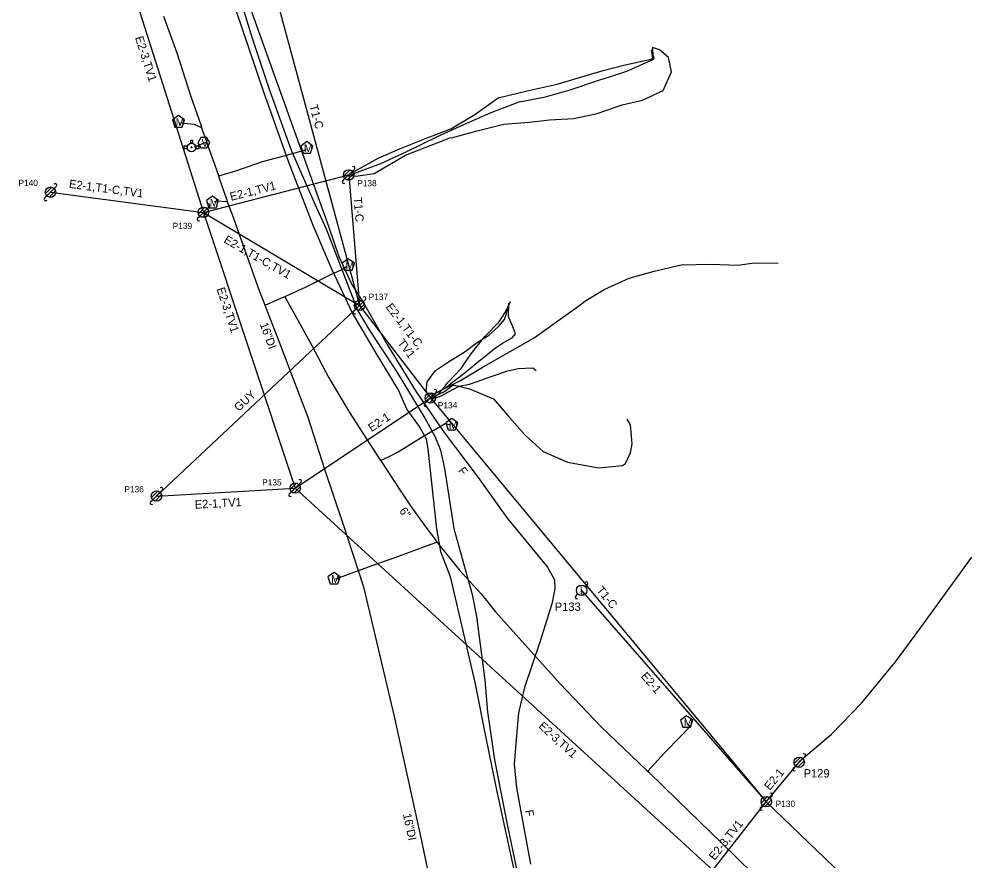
# Model space of a CAD drawing. Extents: x 1741604 to 1825760, y 1164229 to 1194908.
# Drawn here: x 1754886.6 to 1755346.9, y 1170509.7 to 1170914.1 of the extents above; entities that cross this region are included whole.
import ezdxf

# ---------------------------------------------------------------- set-up
doc = ezdxf.new("R2010")
doc.units = 0
for name, color, linetype in [('RD_EX_SU_Elec', 7, 'Continuous'), ('RD_EX_SU_H2O', 7, 'Continuous'), ('RD_EX_SU_Ovhd', 7, 'Continuous'), ('RD_EX_SU_Pole', 7, 'Continuous'), ('RD_EX_SU_Telecom', 7, 'Continuous'), ('RD_EX_SU_TX_H2O', 7, 'Continuous'), ('RD_EX_SU_TX_Pole', 7, 'Continuous'), ('RD_EX_SU_TX_Telecom', 7, 'Continuous')]:
    doc.layers.add(name, color=color, linetype=linetype)

# ---------------------------------------------------------------- blocks, each defined once
blk = doc.blocks.new('SUE_PP')
at = {"layer": 'RD_EX_SU_Pole'}
for p, q in [((-2.41, -0.65), (0.65, 2.41)), ((-1.77, -1.77), (1.77, 1.77)), ((-0.65, -2.41), (2.41, 0.65)), ((1.77, 1.77), (2.83, 2.83)), ((-2.83, -2.83), (-1.77, -1.77))]:
    blk.add_line(p, q, dxfattribs=at)
blk.add_circle((0, 0), 2.5, dxfattribs=at)
for centre, start, end in [((2.3, 3.36), 315, 135), ((-2.3, -3.36), 135, 315)]:
    blk.add_arc(centre, 0.75, start, end, dxfattribs=at)

msp = doc.modelspace()

# ---------------------------------------------------------------- linework, layer by layer
at = {"layer": 'RD_EX_SU_Elec'}
for points in [[(1755044.7, 1170839.23), (1755059.42, 1170847.52), (1755069.97, 1170851.99), (1755081.97, 1170856.73), (1755094.15, 1170861.35), (1755105.68, 1170868.24), (1755116.83, 1170876.23), (1755130.76, 1170879.59), (1755145.27, 1170882.79), (1755157.04, 1170886.35), (1755167.37, 1170889.4), (1755177.92, 1170892.19), (1755190.42, 1170894.89), (1755191.27, 1170895.37), (1755190.53, 1170899.32)], [(1755084.76, 1170733.42), (1755089.15, 1170735.61), (1755098.48, 1170740.34), (1755109.16, 1170746.7), (1755118.99, 1170752.35), (1755127.51, 1170757.14), (1755134.1, 1170760.96), (1755146.67, 1170769.95), (1755155.55, 1170776.25), (1755158.59, 1170778.65), (1755167.83, 1170784.2), (1755179.88, 1170789.61), (1755191.9, 1170793.03), (1755204.81, 1170796.12), (1755219.13, 1170796.38), (1755232.05, 1170795.84), (1755239.93, 1170796.97), (1755251.49, 1170796.86)], [(1755084.91, 1170731.92), (1755087.35, 1170733.19), (1755090.32, 1170736.35), (1755092.73, 1170739.5), (1755099.15, 1170746.28), (1755103.76, 1170753.16), (1755110.39, 1170761.57), (1755117.38, 1170768.69), (1755120.2, 1170773.08), (1755122.8, 1170778.49)], [(1755084.11, 1170731.83), (1755085.97, 1170731.91), (1755088.75, 1170732.77), (1755092.98, 1170735.1), (1755098.13, 1170737.74), (1755103.12, 1170738.67), (1755106.73, 1170740), (1755113.51, 1170742.36), (1755121.53, 1170745.15), (1755126.71, 1170746.19), (1755133.52, 1170746.54), (1755135.08, 1170745.23)], [(1755261.47, 1170557.34), (1755277.07, 1170570.46), (1755291.51, 1170585.36), (1755307.86, 1170605.28), (1755320.07, 1170621.78), (1755344.55, 1170655.55)]]:
    msp.add_lwpolyline(points, dxfattribs=at)
at = {"layer": 'RD_EX_SU_H2O'}
for p, q in [((1754967.44, 1170853.08), (1754965.8, 1170853.08)), ((1754965.8, 1170853.08), (1754965.8, 1170852.03)), ((1754968.97, 1170855.86), (1754968.97, 1170854.52)), ((1754970.02, 1170855.86), (1754968.97, 1170855.86)), ((1754970.02, 1170854.49), (1754970.02, 1170855.86)), ((1754970.88, 1170852.82), (1754976.78, 1170855.16)), ((1754973.15, 1170853.08), (1754971.46, 1170853.08)), ((1754973.15, 1170852.03), (1754973.15, 1170853.08)), ((1754965.8, 1170852.03), (1754967.4, 1170852.03)), ((1754971.5, 1170852.03), (1754973.15, 1170852.03))]:
    msp.add_line(p, q, dxfattribs=at)
for points in [[(1754956.06, 1170915.61), (1754962.38, 1170897.97), (1754969.17, 1170876.92), (1754973.9, 1170863.31), (1754974.6, 1170860.97), (1754976.54, 1170856.02), (1754977.05, 1170854.22), (1754979.81, 1170846.24), (1754982.34, 1170839.52), (1754982.8, 1170837.72), (1754986.07, 1170828.02), (1754986.99, 1170825.47), (1754988.93, 1170820.19), (1755002.08, 1170783.29), (1755004.4, 1170777.61), (1755005.1, 1170775.84), (1755011.46, 1170759.4), (1755019.59, 1170737.92), (1755025.36, 1170722.87), (1755033.31, 1170697.84), (1755042.14, 1170671.77)], [(1754963.77, 1170864.49), (1754965.97, 1170864.08), (1754970.66, 1170863.71), (1754974.26, 1170862.11)], [(1754982.53, 1170838.76), (1754990.75, 1170841.23), (1755003.57, 1170845.66), (1755016.43, 1170849.11), (1755024.71, 1170851.52)], [(1754986.66, 1170826.38), (1754981.58, 1170826.63), (1754980.39, 1170826.13)], [(1755004.79, 1170776.74), (1755012.45, 1170780.01), (1755015.18, 1170781.14), (1755024.31, 1170785.39), (1755037.39, 1170791.92), (1755041.3, 1170793.55), (1755044.15, 1170795.36)], [(1755014.24, 1170780.75), (1755019.67, 1170771.18), (1755027.37, 1170757.25), (1755035.4, 1170741.69), (1755045.44, 1170725.1), (1755059.91, 1170702.52), (1755060.75, 1170701.38), (1755069.67, 1170687.97), (1755075.12, 1170679.72), (1755082.62, 1170669.44), (1755086.66, 1170663.95), (1755087.69, 1170662.44), (1755098.04, 1170649.52), (1755108.67, 1170637.95), (1755115.51, 1170629.29), (1755146.69, 1170594.66), (1755166.41, 1170574.06), (1755188.2, 1170553.24), (1755189.2, 1170552.26), (1755202.99, 1170538.84), (1755224.11, 1170518.52), (1755246.97, 1170496)], [(1755060.31, 1170701.97), (1755064.52, 1170704.03), (1755068.81, 1170706.14), (1755080.57, 1170713.54), (1755091.39, 1170719.75), (1755093.83, 1170719.16)], [(1755042.14, 1170671.77), (1755052.06, 1170641.32), (1755066.9, 1170578.97), (1755079.96, 1170519.29), (1755092.63, 1170458.3), (1755105.45, 1170397.86), (1755116.43, 1170325.12), (1755123.37, 1170260.52), (1755129.9, 1170197.98), (1755130.76, 1170187.84), (1755130.94, 1170186.34), (1755135.98, 1170128.29), (1755137.6, 1170105.08), (1755122.59, 1170093.04)], [(1755038.81, 1170645.21), (1755056.35, 1170651.65), (1755068.64, 1170655.9), (1755082.42, 1170661), (1755087.41, 1170662.85)], [(1755188.74, 1170552.71), (1755196.87, 1170561.52), (1755204.69, 1170569.58), (1755209.12, 1170574.23), (1755207.59, 1170575.88)]]:
    msp.add_lwpolyline(points, dxfattribs=at)
for points in [[(1754963.21, 1170867.78), (1754960.3, 1170865.67), (1754961.41, 1170862.26), (1754965, 1170862.26), (1754966.11, 1170865.67)], [(1754978.33, 1170854.71), (1754976.89, 1170857.21), (1754974, 1170857.21), (1754972.56, 1170854.71), (1754974, 1170852.21), (1754976.89, 1170852.21)], [(1755024.87, 1170855.24), (1755021.97, 1170853.13), (1755023.08, 1170849.72), (1755026.66, 1170849.72), (1755027.77, 1170853.13)], [(1754979.59, 1170829.03), (1754976.69, 1170826.92), (1754977.8, 1170823.51), (1754981.38, 1170823.51), (1754982.49, 1170826.92)], [(1755044.83, 1170798.96), (1755041.93, 1170796.85), (1755043.04, 1170793.44), (1755046.62, 1170793.44), (1755047.73, 1170796.85)], [(1755094.56, 1170722.28), (1755091.66, 1170720.17), (1755092.76, 1170716.76), (1755096.35, 1170716.76), (1755097.46, 1170720.17)], [(1755037.96, 1170648.25), (1755035.06, 1170646.14), (1755036.17, 1170642.73), (1755039.75, 1170642.73), (1755040.86, 1170646.14)], [(1755207.46, 1170579.4), (1755204.56, 1170577.29), (1755205.67, 1170573.88), (1755209.26, 1170573.88), (1755210.36, 1170577.29)]]:
    msp.add_lwpolyline(points, close=True, dxfattribs=at)
for radius in [2.1, 0.263]:
    msp.add_circle((1754969.45, 1170852.47), radius, dxfattribs=at)
for start, end in [(163.3387, 192.315), (74.2455, 103.2128), (347.685, 16.6613)]:
    msp.add_arc((1754969.45, 1170852.47), 2.1, start, end, dxfattribs=at)
at = {"layer": 'RD_EX_SU_Ovhd'}
for p, q in [((1754936.53, 1170943.16), (1754975.2, 1170821.28)), ((1755009.84, 1170925.6), (1755050.22, 1170776.56)), ((1754975.2, 1170821.28), (1755045, 1170839.26)), ((1755045, 1170839.26), (1755050.22, 1170776.56)), ((1754901.67, 1170830.96), (1754975.2, 1170821.28)), ((1754975.2, 1170821.28), (1755050.22, 1170776.56)), ((1754975.2, 1170821.28), (1755019.3, 1170688.81)), ((1754952.64, 1170684.97), (1755050.22, 1170776.56)), ((1755050.22, 1170776.56), (1755084.28, 1170732.08)), ((1755019.3, 1170688.81), (1755084.28, 1170732.08)), ((1755084.28, 1170732.08), (1755245.71, 1170538.1)), ((1754952.64, 1170684.97), (1755019.3, 1170688.81)), ((1755019.3, 1170688.81), (1755220.03, 1170505.23)), ((1755156.98, 1170639.65), (1755245.71, 1170538.1)), ((1755245.71, 1170538.1), (1755261.53, 1170557.04)), ((1755220.03, 1170505.23), (1755245.71, 1170538.1)), ((1755245.71, 1170538.1), (1755346.94, 1170440.97))]:
    msp.add_line(p, q, dxfattribs=at)
at = {"layer": 'RD_EX_SU_Pole'}
for p, q in [((1755042.58, 1170838.61), (1755045.65, 1170841.68)), ((1755043.23, 1170837.49), (1755046.77, 1170841.03)), ((1755044.35, 1170836.85), (1755047.41, 1170839.91)), ((1755046.77, 1170841.03), (1755047.83, 1170842.09)), ((1755042.17, 1170836.43), (1755043.23, 1170837.49)), ((1755081.87, 1170731.43), (1755084.93, 1170734.49)), ((1755082.51, 1170730.31), (1755086.05, 1170733.84)), ((1755086.05, 1170733.84), (1755087.11, 1170734.9)), ((1755081.45, 1170729.25), (1755082.51, 1170730.31)), ((1755083.63, 1170729.66), (1755086.7, 1170732.72)), ((1755158.75, 1170641.42), (1755159.81, 1170642.48)), ((1755154.15, 1170636.83), (1755155.21, 1170637.89))]:
    msp.add_line(p, q, dxfattribs=at)
for centre in [(1755045, 1170839.26), (1755084.28, 1170732.08), (1755156.98, 1170639.65)]:
    msp.add_circle(centre, 2.5, dxfattribs=at)
for centre, start, end in [((1755047.3, 1170842.62), 315, 135), ((1755042.7, 1170835.9), 135, 315), ((1755086.58, 1170735.43), 315, 135), ((1755081.98, 1170728.72), 135, 315), ((1755159.28, 1170643.01), 315, 135), ((1755154.68, 1170636.3), 135, 315)]:
    msp.add_arc(centre, 0.75, start, end, dxfattribs=at)
at = {"layer": 'RD_EX_SU_Telecom'}
for points in [[(1754967.13, 1170994.05), (1754974.43, 1170968.95), (1754987.04, 1170929.46), (1755004.13, 1170879.16), (1755015.94, 1170845.8), (1755027.84, 1170815.17), (1755036.74, 1170794.1), (1755046.9, 1170772.73), (1755058.13, 1170753.54), (1755068.96, 1170735.75), (1755072.88, 1170726.57), (1755079.23, 1170717.91), (1755082.2, 1170712.4), (1755082.99, 1170707.43), (1755087.24, 1170669.18), (1755089.17, 1170658.27), (1755093.84, 1170646.29), (1755105.7, 1170595.36), (1755111, 1170568.73), (1755116.38, 1170542.14), (1755124.51, 1170504.65), (1755130.68, 1170470.03), (1755139.68, 1170422.81)], [(1754989.66, 1170942.34), (1755001.61, 1170908.39), (1755035.52, 1170814.23), (1755040.32, 1170800.04), (1755046.58, 1170786.61), (1755052.71, 1170776.7), (1755063.97, 1170756.98), (1755077.38, 1170735), (1755090.96, 1170715.53), (1755107.27, 1170693.89), (1755121.25, 1170674.35), (1755140.61, 1170650.74), (1755144.01, 1170644.65), (1755144.02, 1170640.39), (1755142.64, 1170633.11), (1755137.09, 1170615.19), (1755129.59, 1170592.91), (1755126.56, 1170580.85), (1755125.53, 1170568), (1755124.55, 1170556.1), (1755125.66, 1170544.73), (1755132.36, 1170508.03)], [(1754990.73, 1170930.67), (1754998.66, 1170905.01), (1755006.82, 1170880.46), (1755017.33, 1170851.11), (1755028.92, 1170824.86), (1755034.21, 1170813.32), (1755042.89, 1170790.87), (1755049.31, 1170774.25), (1755054.9, 1170764.86), (1755068.27, 1170744.38), (1755081.53, 1170722.42), (1755086.38, 1170713.73), (1755089.14, 1170706.97), (1755091.1, 1170698.27), (1755095.61, 1170669.4), (1755104.32, 1170637.7), (1755106.48, 1170627.02), (1755110.45, 1170596.46), (1755111.79, 1170581.3), (1755115.03, 1170558.13), (1755121.12, 1170527.09), (1755125.84, 1170504.97)], [(1755044.96, 1170839.04), (1755060.53, 1170844.8), (1755072.63, 1170850.4), (1755087.77, 1170857.76), (1755100.36, 1170863.53), (1755113.43, 1170869.18), (1755127.03, 1170874.33), (1755139.59, 1170876.74), (1755151.97, 1170880.24), (1755165.7, 1170884.94), (1755169.93, 1170886.23), (1755178.63, 1170889.07), (1755190.93, 1170894.56), (1755191.88, 1170895.42), (1755191.31, 1170896.87), (1755191.14, 1170900.26)], [(1755045.16, 1170839.16), (1755048.5, 1170838.63), (1755057.3, 1170839.89), (1755072.32, 1170848.71), (1755094.13, 1170857.27), (1755094.38, 1170857.14), (1755106.77, 1170860.49), (1755119.62, 1170863.63), (1755131.82, 1170864.59), (1755141.51, 1170865.71), (1755153.27, 1170866.37), (1755164.52, 1170868.73), (1755176.53, 1170872.91), (1755186.28, 1170875.11), (1755196.1, 1170879.88), (1755200.25, 1170888.75), (1755198.69, 1170895.74), (1755194.47, 1170899.35), (1755190.97, 1170900.47)], [(1755083.67, 1170732.7), (1755082.24, 1170735.28), (1755082.78, 1170739.91), (1755086.8, 1170745.28), (1755093.03, 1170749.4), (1755101, 1170754.35), (1755106.35, 1170758.4), (1755112.23, 1170762.1), (1755116.99, 1170766.45), (1755119.87, 1170769.79), (1755120.86, 1170772.65), (1755121.48, 1170775.76)], [(1755085.29, 1170733.01), (1755087.12, 1170734.51), (1755089.36, 1170735.75), (1755091.98, 1170737.24), (1755094.99, 1170739.85), (1755098.08, 1170742.02), (1755103.7, 1170746.53), (1755106.76, 1170749.14), (1755109.65, 1170751.43), (1755114.88, 1170755.64), (1755119.02, 1170758.45), (1755123.8, 1170761.07), (1755125.26, 1170762.82), (1755124.22, 1170765.54), (1755121.8, 1170771.17), (1755121.92, 1170777.71)], [(1755085.41, 1170732.59), (1755091.05, 1170735.15), (1755095.3, 1170738.34), (1755098.54, 1170737.66), (1755103, 1170736.4), (1755114.6, 1170731.7), (1755122.27, 1170722.73), (1755129.72, 1170714.33), (1755138.51, 1170706.38), (1755150.14, 1170701.27), (1755165.19, 1170698.57), (1755176.63, 1170699.59), (1755178.04, 1170700.64), (1755180.49, 1170705.64), (1755181.24, 1170710.01), (1755180.4, 1170719.19), (1755178.9, 1170721.85)]]:
    msp.add_lwpolyline(points, dxfattribs=at)

# ---------------------------------------------------------------- block references
at = {"layer": 'RD_EX_SU_Pole'}
for p in [(1754901.67, 1170830.96), (1754975.2, 1170821.28), (1755050.22, 1170776.56), (1755019.3, 1170688.81), (1754952.64, 1170684.97), (1755261.53, 1170557.04), (1755245.71, 1170538.1)]:
    msp.add_blockref('SUE_PP', p, dxfattribs=at)

# ---------------------------------------------------------------- texts
at = {"layer": 'RD_EX_SU_H2O'}
for s, p in [('M', (1754961.84, 1170862.74)), ('V', (1754974.24, 1170852.83)), ('M', (1755023.5, 1170850.2)), ('M', (1754978.22, 1170823.99)), ('M', (1755043.46, 1170793.92)), ('M', (1755093.19, 1170717.23)), ('M', (1755036.59, 1170643.21)), ('M', (1755206.09, 1170574.35))]:
    msp.add_text(s, height=3.75, dxfattribs=at).set_placement(p)
at = {"layer": 'RD_EX_SU_Ovhd'}
for s, rotation, p in [('E2-3,TV1', 287.6005, (1754942.27, 1170905.23)), ('T1-C', 285.1581, (1755026.07, 1170872.47)), ('E2-1,T1-C,TV1', 352.502, (1754910.39, 1170833.08)), ('E2-1,TV1', 14.446, (1754988.49, 1170826.77)), ('T1-C', 274.76, (1755047.34, 1170828.38)), ('E2-1,T1-C,TV1', 330.2978, (1754984.64, 1170806.97)), ('E2-3,TV1', 288.4116, (1754981.46, 1170784.49)), ('E2-1,T1-C,', 307.4385, (1755062.58, 1170775.73)), ('TV1', 307.4385, (1755068.23, 1170758.49)), ('GUY', 43.187, (1754992.19, 1170725.35)), ('E2-1', 33.6558, (1755056.01, 1170715.66)), ('E2-1,TV1', 3.2962, (1754971.13, 1170678.84)), ('T1-C', 309.7661, (1755163.86, 1170639.57)), ('E2-1', 311.1414, (1755185.22, 1170598.21)), ('E2-3,TV1', 317.5559, (1755135.96, 1170573.98)), ('E2-1', 50.1424, (1755247.43, 1170543.28)), ('E2-3,TV1', 52.0038, (1755220.9, 1170509.58))]:
    msp.add_text(s, height=4, rotation=rotation, dxfattribs=at).set_placement(p)
at = {"layer": 'RD_EX_SU_Pole'}
msp.add_text('L', height=4, dxfattribs=at).set_placement((1755156.12, 1170637.65))
at = {"layer": 'RD_EX_SU_TX_H2O'}
for s, rotation, p in [('16"DI', 290.062, (1755002.22, 1170767.58)), ('6"', 306.1361, (1755069.13, 1170677.75)), ('16"DI', 282.3354, (1755071.03, 1170532.01))]:
    msp.add_text(s, height=4, rotation=rotation, dxfattribs=at).set_placement(p)
at = {"layer": 'RD_EX_SU_TX_Pole'}
for s, height, p in [('P140', 3, (1754886.28, 1170833.93)), ('P138', 3, (1755049.09, 1170833.79)), ('P139', 3, (1754960.41, 1170813.24)), ('P137', 3, (1755054.57, 1170779.17)), ('P134', 3, (1755087.84, 1170727.07)), ('P135', 3, (1755003.42, 1170690.04)), ('P136', 3, (1754937.19, 1170686.74)), ('P133', 4, (1755144.04, 1170629.77)), ('P129', 4, (1755263.67, 1170549.72)), ('P130', 3, (1755250.23, 1170535.56))]:
    msp.add_text(s, height=height, dxfattribs=at).set_placement(p)
at = {"layer": 'RD_EX_SU_TX_Telecom'}
for rotation, p in [(306.9994, (1755097.39, 1170697.03)), (280.3457, (1755129.69, 1170533.82))]:
    msp.add_text('F', height=4, rotation=rotation, dxfattribs=at).set_placement(p)

doc.saveas('drawing.dxf')
